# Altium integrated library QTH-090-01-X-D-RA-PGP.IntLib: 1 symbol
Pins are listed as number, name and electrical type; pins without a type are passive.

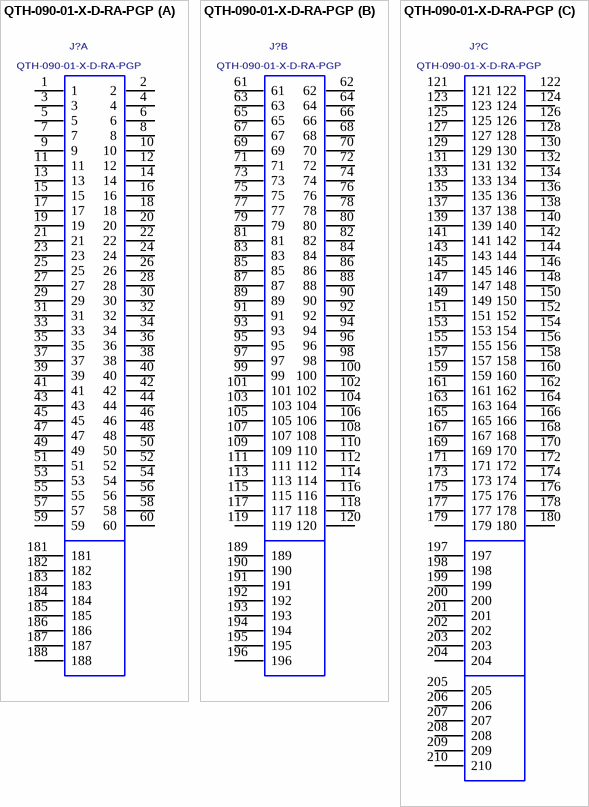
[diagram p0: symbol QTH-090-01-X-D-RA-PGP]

## QTH-090-01-X-D-RA-PGP
designator J?
RIGHT ANGLE TERMINAL STRIP, .5mm PITCH, 180 PINS.; MANUFACTURER: SAMTEC
footprint QTH-090-01-X-D-RA-PGP
part A pins: 1, 2, 3, 4, 5, 6, 7, 8, 9, 10, 11, 12, 13, 14, 15, 16, 17, 18, 19, 20, 21, 22, 23, 24, 25, 26, 27, 28, 29, 30, 31, 32, 33, 34, 35, 36, 37, 38, 39, 40, 41, 42, 43, 44, 45, 46, 47, 48, 49, 50, 51, 52, 53, 54, 55, 56, 57, 58, 59, 60, 181, 182, 183, 184, 185, 186, 187, 188
part B pins: 61, 62, 63, 64, 65, 66, 67, 68, 69, 70, 71, 72, 73, 74, 75, 76, 77, 78, 79, 80, 81, 82, 83, 84, 85, 86, 87, 88, 89, 90, 91, 92, 93, 94, 95, 96, 97, 98, 99, 100, 101, 102, 103, 104, 105, 106, 107, 108, 109, 110, 111, 112, 113, 114, 115, 116, 117, 118, 119, 120, 189, 190, 191, 192, 193, 194, 195, 196
part C pins: 121, 122, 123, 124, 125, 126, 127, 128, 129, 130, 131, 132, 133, 134, 135, 136, 137, 138, 139, 140, 141, 142, 143, 144, 145, 146, 147, 148, 149, 150, 151, 152, 153, 154, 155, 156, 157, 158, 159, 160, 161, 162, 163, 164, 165, 166, 167, 168, 169, 170, 171, 172, 173, 174, 175, 176, 177, 178, 179, 180, 197, 198, 199, 200, 201, 202, 203, 204, 205, 206, 207, 208, 209, 210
